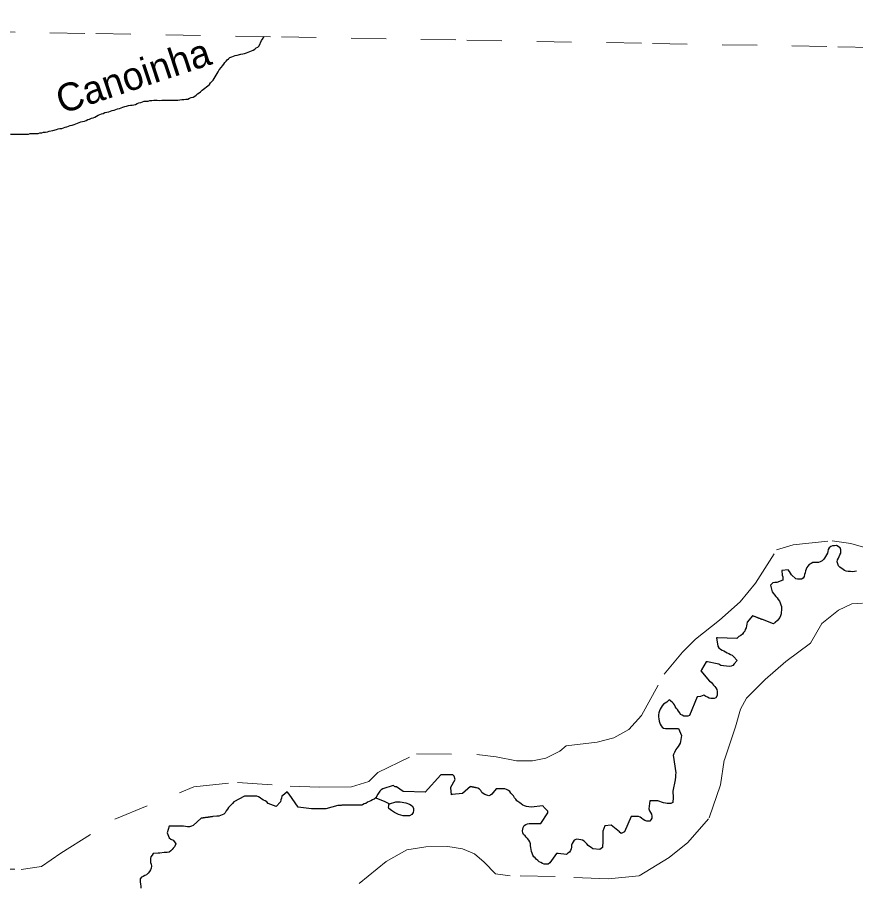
# Model space of a CAD drawing. Extents: x 785.9 to 812.4, y 7674.9 to 7703.1.
# Drawn here: x 796.248 to 798.65, y 7700.434 to 7702.926 of the extents above; entities that cross this region are included whole.
import ezdxf
from ezdxf.enums import TextEntityAlignment as Align

# ---------------------------------------------------------------- set-up
doc = ezdxf.new("R2010")
doc.units = 0
doc.header["$LTSCALE"] = 0.04
doc.linetypes.add('SHORT_DASHED', pattern=[2.7, 1.5, -1.2])
for name, color, linetype, lineweight in [('2', 7, 'Continuous', 25), ('21', 7, 'SHORT_DASHED', 13), ('53', 7, 'SHORT_DASHED', 13), ('7', 7, 'Continuous', 25)]:
    doc.layers.add(name, color=color, linetype=linetype, lineweight=lineweight)
doc.layers.add('61', color=7, linetype='Continuous')

msp = doc.modelspace()

# ---------------------------------------------------------------- linework, layer by layer
at = {"layer": '2'}
msp.add_lwpolyline([(797.3143, 7700.6715), (797.3329, 7700.6769), (797.3451, 7700.6774), (797.3616, 7700.6746), (797.372, 7700.6707), (797.3792, 7700.6653), (797.3831, 7700.6586), (797.3834, 7700.6518), (797.3821, 7700.6461), (797.3779, 7700.641), (797.3712, 7700.6373), (797.3637, 7700.6368), (797.3536, 7700.6373), (797.3402, 7700.6412), (797.3283, 7700.6466), (797.3197, 7700.6521), (797.3127, 7700.658), (797.3119, 7700.6613), (797.3124, 7700.6657), (797.3127, 7700.6681)], close=True, dxfattribs=at)
at = {"layer": '21'}
for points in [[(796.1409, 7700.4844), (796.2583, 7700.4834), (796.317, 7700.4912), (796.3727, 7700.5303), (796.5273, 7700.6271), (796.7532, 7700.7201), (796.8784, 7700.7328), (797.0299, 7700.722), (797.114, 7700.7191), (797.205, 7700.7201), (797.2549, 7700.7357), (797.2813, 7700.7612), (797.3918, 7700.815), (797.5649, 7700.813), (797.6196, 7700.8062), (797.6783, 7700.7945), (797.7243, 7700.7945), (797.7624, 7700.8023), (797.8025, 7700.8228), (797.8211, 7700.8375), (797.9091, 7700.8483), (797.957, 7700.8609), (798, 7700.8844), (798.0362, 7700.9245), (798.1017, 7701.0429), (798.1536, 7701.1065), (798.1917, 7701.1436), (798.2602, 7701.1984), (798.3189, 7701.2503), (798.3629, 7701.3041), (798.4235, 7701.4), (798.4714, 7701.4137), (798.5829, 7701.4254), (798.6367, 7701.4176), (798.71, 7701.3961)], [(798.67, 7701.2464), (798.6397, 7701.2445), (798.6016, 7701.2269), (798.5536, 7701.1887), (798.5214, 7701.132), (798.45, 7701.0792), (798.3913, 7701.0283), (798.3375, 7700.9745), (798.3199, 7700.9432), (798.3062, 7700.8923), (798.2739, 7700.7965), (798.2632, 7700.726), (798.2289, 7700.6282), (798.1693, 7700.5607), (798.1155, 7700.5176), (798.0294, 7700.4648), (797.9424, 7700.456), (797.7888, 7700.4629), (797.6598, 7700.4649), (797.6177, 7700.4707), (797.5854, 7700.504), (797.558, 7700.5275), (797.5238, 7700.5421), (797.4818, 7700.549), (797.4182, 7700.548), (797.3644, 7700.5392), (797.3048, 7700.5059), (797.1121, 7700.3494)]]:
    msp.add_lwpolyline(points, dxfattribs=at)
at = {"layer": '53'}
msp.add_lwpolyline([(793.8148, 7702.9265), (794.3464, 7702.9173), (794.8781, 7702.9079), (795.4097, 7702.8986), (795.9413, 7702.8893), (796.473, 7702.8799), (797.0046, 7702.8705), (797.5363, 7702.8612), (798.0679, 7702.8517), (798.5996, 7702.8423), (799.1312, 7702.8329)], dxfattribs=at)
at = {"layer": '7'}
for points in [[(796.4202, 7702.6228), (796.4251, 7702.6252), (796.43, 7702.6268), (796.4348, 7702.6284), (796.4405, 7702.6292), (796.4453, 7702.6308), (796.4502, 7702.6333), (796.455, 7702.6349), (796.4599, 7702.6373), (796.4647, 7702.6389), (796.4696, 7702.6406), (796.4745, 7702.643), (796.4793, 7702.6462), (796.4842, 7702.6478), (796.489, 7702.6495), (796.4939, 7702.6511), (796.4987, 7702.6535), (796.5044, 7702.6543), (796.5101, 7702.6559), (796.5149, 7702.6575), (796.5198, 7702.6592), (796.5254, 7702.6608), (796.5303, 7702.6624), (796.5351, 7702.664), (796.5408, 7702.6656), (796.5505, 7702.6689), (796.5554, 7702.6713), (796.561, 7702.6721), (796.5659, 7702.6737), (796.5716, 7702.6745), (796.5772, 7702.6745), (796.5861, 7702.677), (796.591, 7702.6794), (796.5958, 7702.681), (796.6015, 7702.6826), (796.6063, 7702.6842), (796.6112, 7702.6859), (796.6169, 7702.6867), (796.6225, 7702.6867), (796.6274, 7702.6883), (796.6331, 7702.6883), (796.6387, 7702.6891), (796.6484, 7702.6891), (796.6541, 7702.6883), (796.6622, 7702.6891), (796.7075, 7702.6891), (796.7132, 7702.6899), (796.7196, 7702.6907), (796.7253, 7702.6915), (796.731, 7702.6923), (796.7366, 7702.6923), (796.7415, 7702.6948), (796.7463, 7702.6964), (796.7512, 7702.698), (796.756, 7702.7004), (796.7601, 7702.7037), (796.7641, 7702.7069), (796.769, 7702.7101), (796.773, 7702.7134), (796.7771, 7702.7174), (796.7811, 7702.7207), (796.7852, 7702.7239), (796.79, 7702.7271), (796.7941, 7702.7304), (796.7981, 7702.7344), (796.8014, 7702.7385), (796.8054, 7702.7425), (796.8086, 7702.7465), (796.8119, 7702.7514), (796.8143, 7702.7563), (796.8175, 7702.7611), (796.8208, 7702.766), (796.8232, 7702.7708), (796.8264, 7702.7757), (796.8329, 7702.7838), (796.8361, 7702.7878), (796.8394, 7702.7927), (796.8426, 7702.7967), (796.8459, 7702.8008), (796.8491, 7702.8048), (796.8531, 7702.808), (796.8572, 7702.8113), (796.862, 7702.8137), (796.8669, 7702.8153), (796.8717, 7702.8169), (796.8782, 7702.8178), (796.8879, 7702.821), (796.8936, 7702.8218), (796.8985, 7702.8234), (796.9041, 7702.825), (796.909, 7702.8267), (796.9138, 7702.8283), (796.9187, 7702.8307), (796.9235, 7702.8323), (796.9284, 7702.8356), (796.9324, 7702.8388), (796.9373, 7702.8412), (796.9405, 7702.8453), (796.9478, 7702.8598), (796.95, 7702.8642), (796.9548, 7702.8714)], [(796.2285, 7702.592), (796.2795, 7702.592), (796.2843, 7702.5936), (796.307, 7702.5936), (796.3118, 7702.5952), (796.3175, 7702.5952), (796.3223, 7702.5969), (796.328, 7702.5977), (796.3337, 7702.5985), (796.3385, 7702.6001), (796.3499, 7702.6017), (796.3596, 7702.6049), (796.3644, 7702.6066), (796.3693, 7702.6082), (796.3749, 7702.6082), (796.3798, 7702.6098), (796.3846, 7702.6114), (796.3895, 7702.613), (796.3992, 7702.6163), (796.4049, 7702.6179), (796.4105, 7702.6195), (796.4154, 7702.6211), (796.4202, 7702.6228)], [(798.5952, 7701.4123), (798.5896, 7701.4115), (798.5839, 7701.4115), (798.579, 7701.409), (798.5742, 7701.4058), (798.5718, 7701.4009), (798.5709, 7701.3953), (798.5693, 7701.3904), (798.5669, 7701.3856), (798.5637, 7701.3807), (798.5612, 7701.3759), (798.558, 7701.3718), (798.554, 7701.3678), (798.5491, 7701.3653), (798.5442, 7701.3637), (798.5386, 7701.3629), (798.5273, 7701.3629), (798.5224, 7701.3605), (798.5175, 7701.3573), (798.5135, 7701.3532), (798.5103, 7701.3492), (798.507, 7701.3394), (798.5054, 7701.3338), (798.5038, 7701.3289), (798.503, 7701.3233), (798.4997, 7701.3184), (798.4949, 7701.316), (798.4892, 7701.3152), (798.4836, 7701.3152), (798.4787, 7701.3168), (798.4666, 7701.3281), (798.4609, 7701.3378), (798.4569, 7701.3419), (798.4391, 7701.3403)], [(798.6527, 7701.3386), (798.6413, 7701.337), (798.6357, 7701.3378), (798.6292, 7701.3378), (798.6235, 7701.3386), (798.6187, 7701.3403), (798.6146, 7701.3435), (798.6049, 7701.35), (798.6009, 7701.354), (798.5977, 7701.3653), (798.5985, 7701.371), (798.6009, 7701.3759), (798.6033, 7701.3807), (798.6049, 7701.3856), (798.6074, 7701.3904), (798.6082, 7701.4001), (798.6057, 7701.405), (798.5952, 7701.4123)], [(798.4391, 7701.3403), (798.4399, 7701.3273), (798.4415, 7701.3225), (798.4415, 7701.3208), (798.4415, 7701.3136), (798.4415, 7701.3127), (798.4245, 7701.3063), (798.4188, 7701.3063), (798.4132, 7701.3047), (798.4059, 7701.2982), (798.4107, 7701.2788), (798.4148, 7701.2747), (798.418, 7701.2707), (798.4213, 7701.2658), (798.4253, 7701.2618), (798.4285, 7701.2577), (798.4318, 7701.2529), (798.4342, 7701.248), (798.4358, 7701.2424), (798.4374, 7701.2375), (798.4382, 7701.2318), (798.4382, 7701.2262), (798.4366, 7701.2213), (798.4366, 7701.2157), (798.435, 7701.2108), (798.4326, 7701.2059), (798.4293, 7701.2011), (798.4261, 7701.197), (798.4196, 7701.1914), (798.4184, 7701.1903), (798.4172, 7701.1892), (798.416, 7701.1882), (798.4148, 7701.1871), (798.3832, 7701.1995), (798.3832, 7701.1995), (798.3817, 7701.2001), (798.3802, 7701.2006), (798.3787, 7701.2012), (798.3772, 7701.2018), (798.3757, 7701.2024), (798.3742, 7701.203), (798.3727, 7701.2036), (798.3712, 7701.2042), (798.3697, 7701.2048), (798.3682, 7701.2054), (798.3667, 7701.206), (798.3651, 7701.2065), (798.3636, 7701.2071), (798.3621, 7701.2077), (798.3606, 7701.2083), (798.3591, 7701.2089), (798.3576, 7701.2095), (798.3561, 7701.2101), (798.3546, 7701.2107), (798.3395, 7701.1922), (798.3387, 7701.1865), (798.3371, 7701.1817), (798.3363, 7701.176), (798.3339, 7701.1711), (798.3323, 7701.1663), (798.329, 7701.1622), (798.3258, 7701.1574), (798.3217, 7701.1542), (798.3153, 7701.1509), (798.3096, 7701.1453), (798.2546, 7701.1477), (798.2546, 7701.1477), (798.253, 7701.1478), (798.2513, 7701.1478), (798.2554, 7701.1234), (798.2578, 7701.1186), (798.2627, 7701.1153), (798.2675, 7701.1121), (798.2724, 7701.1097), (798.2772, 7701.1072), (798.2821, 7701.1048), (798.2869, 7701.1024), (798.2918, 7701.0999), (798.2966, 7701.0975), (798.3007, 7701.0935), (798.3112, 7701.0821), (798.3023, 7701.0724), (798.2983, 7701.0684), (798.2934, 7701.066), (798.2877, 7701.0651), (798.2877, 7701.0651), (798.2635, 7701.0684), (798.2586, 7701.0716), (798.2538, 7701.0732), (798.2254, 7701.0781), (798.2254, 7701.0781), (798.2239, 7701.0784), (798.2223, 7701.0786), (798.2085, 7701.0554), (798.2085, 7701.0554), (798.2076, 7701.054), (798.2068, 7701.0527), (798.2311, 7701.0231), (798.236, 7701.0198), (798.24, 7701.0158), (798.2432, 7701.0117)], [(798.2432, 7701.0117), (798.2465, 7701.0077), (798.2497, 7701.0037), (798.2521, 7700.9988), (798.253, 7700.9931), (798.2538, 7700.9818), (798.2497, 7700.9753), (798.2449, 7700.9729), (798.2352, 7700.9729), (798.2303, 7700.9745), (798.2254, 7700.977), (798.2206, 7700.9794), (798.2149, 7700.9826), (798.206, 7700.9794), (798.1963, 7700.9778), (798.1745, 7700.9244), (798.1696, 7700.9227), (798.1583, 7700.9227), (798.1534, 7700.9252), (798.1486, 7700.9276), (798.1461, 7700.9325), (798.1429, 7700.9373), (798.1397, 7700.9414), (798.1364, 7700.9454), (798.1332, 7700.9503), (798.1316, 7700.9551), (798.1283, 7700.9592), (798.1243, 7700.9624), (798.1162, 7700.9697), (798.1089, 7700.9632), (798.1041, 7700.96), (798.0992, 7700.9567), (798.096, 7700.9519), (798.0927, 7700.9478), (798.0903, 7700.943), (798.0879, 7700.9381), (798.0863, 7700.9325), (798.0855, 7700.9268), (798.0855, 7700.9211), (798.0863, 7700.9146), (798.0871, 7700.9082), (798.0903, 7700.9001), (798.0927, 7700.8952), (798.096, 7700.8912), (798.1, 7700.8879), (798.1057, 7700.8871), (798.1089, 7700.8871), (798.1105, 7700.8871), (798.1122, 7700.8871), (798.1138, 7700.8871), (798.1154, 7700.8871), (798.117, 7700.8871), (798.1186, 7700.8871), (798.1203, 7700.8871), (798.1219, 7700.8871), (798.1235, 7700.8871), (798.1251, 7700.8871), (798.1267, 7700.8871), (798.1283, 7700.8871), (798.13, 7700.8871), (798.1316, 7700.8871), (798.1332, 7700.8871), (798.1348, 7700.8871), (798.1364, 7700.8871), (798.1381, 7700.8871), (798.1397, 7700.8871), (798.1413, 7700.8871), (798.1429, 7700.8871), (798.151, 7700.8669), (798.1502, 7700.8612), (798.1494, 7700.8556), (798.1486, 7700.8499), (798.147, 7700.8451), (798.1445, 7700.8402), (798.1413, 7700.8354), (798.1381, 7700.8313), (798.1348, 7700.8273), (798.1308, 7700.8184), (798.1301, 7700.8169), (798.1294, 7700.8154), (798.1288, 7700.8139), (798.1281, 7700.8125), (798.1274, 7700.811), (798.1348, 7700.7601), (798.134, 7700.7544), (798.134, 7700.7488), (798.1332, 7700.7399), (798.1259, 7700.7075), (798.1267, 7700.7018), (798.1275, 7700.6954), (798.1275, 7700.6897), (798.1259, 7700.6751), (798.1211, 7700.6727), (798.1154, 7700.6719), (798.1097, 7700.6719), (798.1049, 7700.6735), (798.0992, 7700.6743), (798.0936, 7700.676), (798.0887, 7700.6784), (798.0838, 7700.68), (798.0814, 7700.68)], [(797.4956, 7700.7544), (797.4924, 7700.7544), (797.4907, 7700.7544), (797.4891, 7700.7544), (797.4875, 7700.7544), (797.4859, 7700.7544), (797.4843, 7700.7544), (797.4827, 7700.7544), (797.481, 7700.7544), (797.4794, 7700.7544), (797.4778, 7700.7544), (797.4762, 7700.7544), (797.4746, 7700.7544), (797.4729, 7700.7544), (797.4713, 7700.7544), (797.4697, 7700.7544), (797.4681, 7700.7544), (797.4665, 7700.7544), (797.4649, 7700.7544), (797.4632, 7700.7544), (797.4616, 7700.7544), (797.4163, 7700.7051), (797.4163, 7700.7051), (797.3548, 7700.7067), (797.3548, 7700.7067), (797.3532, 7700.7067), (797.3346, 7700.7205), (797.3305, 7700.7205), (797.3291, 7700.7213), (797.3278, 7700.7221), (797.3264, 7700.723), (797.325, 7700.7238), (797.2949, 7700.7148), (797.2909, 7700.7116), (797.2868, 7700.7075), (797.2812, 7700.6986), (797.2747, 7700.6889)], [(797.7481, 7700.5028), (797.7432, 7700.5052), (797.7392, 7700.5085), (797.7351, 7700.5125), (797.7319, 7700.5166), (797.7278, 7700.5198), (797.7254, 7700.5246), (797.723, 7700.5295), (797.7213, 7700.5344), (797.7205, 7700.54), (797.7197, 7700.5457), (797.7181, 7700.5513), (797.7181, 7700.557), (797.7165, 7700.5627), (797.7141, 7700.5675), (797.71, 7700.5716), (797.706, 7700.5756), (797.7027, 7700.5797), (797.6987, 7700.5837), (797.6963, 7700.5886), (797.6955, 7700.5942), (797.6971, 7700.6039), (797.7003, 7700.6088), (797.7052, 7700.612), (797.71, 7700.6136), (797.7149, 7700.6153), (797.7205, 7700.6153), (797.7222, 7700.6153), (797.7238, 7700.6153), (797.7254, 7700.6153), (797.727, 7700.6153), (797.7286, 7700.6153), (797.7302, 7700.6153), (797.7319, 7700.6153), (797.7335, 7700.6153), (797.7351, 7700.6153), (797.7367, 7700.6153), (797.7383, 7700.6153), (797.74, 7700.6153), (797.7416, 7700.6153), (797.7432, 7700.6153), (797.7448, 7700.6153), (797.7464, 7700.6153), (797.7481, 7700.6153), (797.7683, 7700.646), (797.7683, 7700.6501), (797.757, 7700.6622), (797.757, 7700.6622), (797.7558, 7700.6634), (797.7547, 7700.6646), (797.7536, 7700.6657), (797.7205, 7700.6622), (797.7068, 7700.6638), (797.7011, 7700.6654), (797.6963, 7700.6679), (797.6914, 7700.6711), (797.6874, 7700.6743), (797.6793, 7700.68), (797.676, 7700.6849), (797.6728, 7700.6889), (797.6696, 7700.6938), (797.6663, 7700.6978), (797.6623, 7700.7018), (797.659, 7700.7067), (797.655, 7700.7099), (797.6501, 7700.7124), (797.6453, 7700.714), (797.6202, 7700.714), (797.6113, 7700.7035), (797.6081, 7700.6994), (797.604, 7700.6962), (797.5992, 7700.6946), (797.5878, 7700.6978), (797.583, 7700.701), (797.5789, 7700.7043), (797.5765, 7700.7091), (797.5725, 7700.7132), (797.5676, 7700.7164), (797.5636, 7700.7172), (797.562, 7700.7175), (797.5604, 7700.7179), (797.5588, 7700.7182), (797.5572, 7700.7185), (797.5556, 7700.7188), (797.554, 7700.7191), (797.5525, 7700.7194), (797.5509, 7700.7198), (797.5493, 7700.7201), (797.5477, 7700.7204), (797.5461, 7700.7207), (797.5231, 7700.701), (797.5231, 7700.701), (797.494, 7700.6978), (797.494, 7700.6978), (797.4924, 7700.6976), (797.4899, 7700.7172), (797.4899, 7700.7172), (797.4897, 7700.7188), (797.5029, 7700.7415), (797.4996, 7700.7504), (797.4956, 7700.7544)], [(796.9243, 7700.6929), (796.9227, 7700.6929), (796.9211, 7700.6929), (796.9195, 7700.6929), (796.9179, 7700.6929), (796.9163, 7700.6929), (796.9146, 7700.6929), (796.913, 7700.6929), (796.9114, 7700.6929), (796.9098, 7700.6929), (796.9082, 7700.6929), (796.9065, 7700.6929), (796.9049, 7700.6929), (796.9033, 7700.6929), (796.9017, 7700.6929), (796.9001, 7700.6929), (796.8985, 7700.6929), (796.8685, 7700.6768), (796.8645, 7700.6727), (796.8604, 7700.6687), (796.8564, 7700.6646), (796.8531, 7700.6606), (796.8499, 7700.6557), (796.8467, 7700.6509), (796.8434, 7700.646), (796.8394, 7700.642), (796.8345, 7700.6395), (796.8297, 7700.6379), (796.8248, 7700.6363), (796.8192, 7700.6363), (796.8078, 7700.6347), (796.8062, 7700.6345), (796.8046, 7700.6342), (796.803, 7700.634), (796.8014, 7700.6338), (796.7998, 7700.6335), (796.7982, 7700.6333), (796.7966, 7700.6331), (796.795, 7700.6329), (796.7934, 7700.6326), (796.7918, 7700.6324), (796.7902, 7700.6322), (796.7886, 7700.6319), (796.787, 7700.6317), (796.7854, 7700.6315), (796.7838, 7700.6313), (796.7822, 7700.631), (796.7806, 7700.6308), (796.779, 7700.6306), (796.7774, 7700.6303), (796.7758, 7700.6301), (796.7742, 7700.6299), (796.752, 7700.6096), (796.7471, 7700.6072), (796.7415, 7700.6056), (796.7358, 7700.6056), (796.7293, 7700.6064), (796.7237, 7700.6072), (796.718, 7700.6072), (796.7172, 7700.6072), (796.7156, 7700.6072), (796.714, 7700.6072), (796.7123, 7700.6072), (796.7107, 7700.6072), (796.7091, 7700.6072), (796.7075, 7700.6072), (796.7059, 7700.6072), (796.7043, 7700.6072), (796.7026, 7700.6072), (796.701, 7700.6072), (796.6994, 7700.6072), (796.6978, 7700.6072), (796.6962, 7700.6072), (796.6945, 7700.6072), (796.6929, 7700.6072), (796.6913, 7700.6072), (796.6897, 7700.6072), (796.6881, 7700.6072), (796.6865, 7700.6072), (796.6848, 7700.6072), (796.6832, 7700.6072), (796.6776, 7700.5878), (796.6808, 7700.5789), (796.6824, 7700.574), (796.6881, 7700.57), (796.6945, 7700.5667), (796.6986, 7700.5627), (796.7018, 7700.557), (796.6978, 7700.5481), (796.6945, 7700.5441), (796.6913, 7700.54), (796.6873, 7700.5368), (796.6832, 7700.5327), (796.6776, 7700.5319), (796.6687, 7700.5319), (796.6565, 7700.5303), (796.6509, 7700.5303), (796.6371, 7700.5287), (796.6339, 7700.5246), (796.6306, 7700.5198), (796.6298, 7700.5141)], [(797.2747, 7700.6889), (797.2707, 7700.6849), (797.2658, 7700.6832), (797.2609, 7700.68), (797.2561, 7700.6784), (797.2512, 7700.676), (797.2464, 7700.6727), (797.2415, 7700.6711), (797.2367, 7700.6687), (797.2352, 7700.6679), (797.1776, 7700.6671), (797.1776, 7700.6671), (797.176, 7700.667), (797.1744, 7700.667), (797.1728, 7700.667), (797.1711, 7700.667), (797.1695, 7700.6669), (797.1679, 7700.6669), (797.1663, 7700.6669), (797.1323, 7700.6573), (797.1266, 7700.6573), (797.1218, 7700.6573), (797.1202, 7700.6573), (797.1185, 7700.6573), (797.1169, 7700.6573), (797.1153, 7700.6573), (797.1137, 7700.6573), (797.1121, 7700.6573), (797.1104, 7700.6573), (797.1088, 7700.6573), (797.1072, 7700.6573), (797.1056, 7700.6573), (797.104, 7700.6573), (797.1024, 7700.6573), (797.1007, 7700.6573), (797.0991, 7700.6573), (797.0975, 7700.6573), (797.0959, 7700.6573), (797.0943, 7700.6573), (797.0926, 7700.6573), (797.091, 7700.6573), (797.053, 7700.6622), (797.0271, 7700.6994), (797.0206, 7700.7059), (797.0133, 7700.6994), (797.0053, 7700.6929), (797.0044, 7700.6873), (797.0028, 7700.6824), (797.002, 7700.6768), (796.9891, 7700.6638), (796.9664, 7700.6727), (796.9632, 7700.6768), (796.9583, 7700.68), (796.9535, 7700.6816), (796.9486, 7700.6849), (796.9438, 7700.6881), (796.9389, 7700.6913), (796.9341, 7700.6929), (796.9324, 7700.6929), (796.9308, 7700.6929), (796.9292, 7700.6929), (796.9276, 7700.6929), (796.926, 7700.6929), (796.9243, 7700.6929)], [(797.2747, 7700.6889), (797.3006, 7700.678), (797.3143, 7700.6715)], [(798.0814, 7700.68), (798.0798, 7700.68), (798.0782, 7700.68), (798.0766, 7700.68), (798.0749, 7700.68), (798.0733, 7700.68), (798.0717, 7700.68), (798.0701, 7700.68), (798.0685, 7700.68), (798.0669, 7700.68), (798.0652, 7700.68), (798.0636, 7700.68), (798.062, 7700.68), (798.0604, 7700.68), (798.058, 7700.6573), (798.0596, 7700.6517), (798.0628, 7700.6468), (798.0652, 7700.642), (798.066, 7700.6363), (798.066, 7700.6306), (798.0636, 7700.6258), (798.0604, 7700.6217), (798.0523, 7700.6217), (798.0466, 7700.6234), (798.0418, 7700.6266), (798.0369, 7700.6298), (798.0329, 7700.6331), (798.028, 7700.6347), (798.0264, 7700.6347), (798.0248, 7700.6347), (798.0232, 7700.6347), (798.0215, 7700.6347), (798.0199, 7700.6347), (798.0183, 7700.6347), (798.0167, 7700.6347), (798.0151, 7700.6347), (798.0134, 7700.6347), (798.0118, 7700.6347), (798.0102, 7700.6347), (798.0086, 7700.6347), (798.007, 7700.6347), (797.9876, 7700.591), (797.9787, 7700.5861), (797.973, 7700.591), (797.9738, 7700.591), (797.9495, 7700.6104), (797.9495, 7700.6104), (797.9317, 7700.608), (797.9253, 7700.5934), (797.9253, 7700.5878), (797.9253, 7700.5869), (797.9253, 7700.5853), (797.9253, 7700.5837), (797.9253, 7700.5821), (797.9253, 7700.5805), (797.9253, 7700.5789), (797.9253, 7700.5772), (797.9253, 7700.5756), (797.9253, 7700.574), (797.9253, 7700.5724), (797.9253, 7700.5708), (797.9253, 7700.5691), (797.9253, 7700.5675), (797.9253, 7700.5659), (797.9253, 7700.5643), (797.9244, 7700.5457), (797.9172, 7700.5408), (797.8969, 7700.5424), (797.8921, 7700.5457), (797.888, 7700.5489), (797.884, 7700.5522), (797.8799, 7700.5562), (797.8759, 7700.5602), (797.8727, 7700.5643), (797.8678, 7700.5667), (797.8629, 7700.5683), (797.8573, 7700.5691), (797.8516, 7700.57), (797.8435, 7700.5667), (797.8403, 7700.5627), (797.8379, 7700.5578), (797.8362, 7700.553), (797.8362, 7700.5473), (797.8346, 7700.5424), (797.833, 7700.5376), (797.8298, 7700.5327), (797.8257, 7700.5295), (797.8245, 7700.5285), (797.8232, 7700.5275), (797.8219, 7700.5265), (797.7982, 7700.5287), (797.7982, 7700.5287), (797.7966, 7700.5288), (797.795, 7700.529), (797.7934, 7700.5291), (797.7739, 7700.502), (797.7691, 7700.4987), (797.7634, 7700.4987), (797.7578, 7700.4987), (797.7529, 7700.5004), (797.7481, 7700.5028)], [(796.6298, 7700.5141), (796.629, 7700.5085), (796.6298, 7700.5028), (796.6314, 7700.4979), (796.6322, 7700.4923), (796.6314, 7700.4866), (796.6298, 7700.4818), (796.6266, 7700.4769), (796.6225, 7700.4729), (796.6177, 7700.468), (796.6128, 7700.4656), (796.608, 7700.4631), (796.6031, 7700.4607), (796.5999, 7700.4567), (796.5999, 7700.4478), (796.6007, 7700.4413), (796.6015, 7700.4348), (796.6015, 7700.4292)]]:
    msp.add_lwpolyline(points, dxfattribs=at)

# ---------------------------------------------------------------- texts
at = {"layer": '61'}
msp.add_text('Canoinha', height=0.08, rotation=18.366, dxfattribs=at).set_placement((796.5923, 7702.7212), align=Align.CENTER)

doc.saveas('drawing.dxf')
